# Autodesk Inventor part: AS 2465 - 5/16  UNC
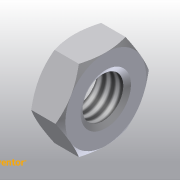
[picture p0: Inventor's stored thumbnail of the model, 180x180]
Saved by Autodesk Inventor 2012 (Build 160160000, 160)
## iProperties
Library Location: C:\Program Files\Local\Autodesk\Inventor 6\content
Library: local
SubLibrary: AS
Family: 79
Member: 20
Member Major Revision: 1
Member Minor Revision: 1
Comments: To add or edit properties for Autodesk Inventor files, use iProperties.
Company: Autodesk
Created: 2002-10
Part Number: AS 2465 - 5/16  UNC
Vendor: Autodesk Inc.
Document SubType Name: Modeling
Designer: Lieven Grauls
Description: Hexagon Thin Nut
Standard: AS 2465 5/16  UNC
Project: Valve Techcamp 2008
Density: 1 g/cm^3
Mass: 0.520705 g
Surface Area: 5.06999 cm^2
Volume: 0.520705 cm^3
Material: Default
Alert: To add or edit properties for Autodesk Inventor files, use iProperties.
Control State: 0
Master: False
Checked Out: False
Shininess: 64.0
Length Units: 11269
Angle Units: 11279
Time Units: 11290
Mass Units: 11283
Length Display Precision: 3
Angle Display Precision: 2
Compacted: True
EGR: 3
Density: 0.0
Volumn: 0.0
Area: 0.0
PropertySet Name: Model Information
Author: Lieven Grauls
Revision Number: 1
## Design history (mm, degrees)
sketch "Sketch1"
  geometry: L1 (-7.332, 0)-(-3.666, 6.35); L2 (-3.666, 6.35)-(3.666, 6.35); L3 (3.666, 6.35)-(7.332, 0); L4 (7.332, 0)-(3.666, -6.35); L5 (3.666, -6.35)-(-3.666, -6.35); L6 (-3.666, -6.35)-(-7.332, 0); 2 further points
  constraints: 12 end point, 1 coincident, 1 horizontal, 11 other
  dimensions: "d0" = 14.6647 distance of L3.end L1.start (= 1.1547 x SW)
extrude "Body" new body sketch "Sketch1" distance "d1" = 4.953 (= KOH); taper "d2" = 0 deg
revolve "Chamfer1" stored, may be unused: angle "d7" = 90 deg
sketch "Sketch3"
  geometry: A1 r 6.35 centre (0, 0) between (-3.175, -5.499) and (3.175, -5.499) reference; 1 further point
  constraints: 1 coincident
hole "Thread" sketch "Sketch3" diameter "d25" = 6.4008; stored, may be unused: countersink angle "d29" = 82 deg, drill point angle "d31" = 118 deg; dims "d26" = 6, "d27" = 4, "d28" = 2, "d30" = 8
node "Volumenkörper1"
node "Volumenkörpern"
node "Oberflächenkörpern"
chamfer "Chamfer2" distance "d8" = 0.76379 (= -0.5 x GD1 + 0.5 x NND); stored, may be unused: angle "d9" = 30 deg, second distance "d40" = 0.76379 (= -0.5 x GD1 + 0.5 x NND)
chamfer "Chamfer3" distance "d10" = 0.76379 (= -0.5 x GD1 + 0.5 x NND); stored, may be unused: angle "d11" = 30 deg, second distance "d41" = 0.76379 (= -0.5 x GD1 + 0.5 x NND)
sketch "Sketch2"
  geometry: L1 (0, 3.666)-(0, 7.332) reference; L2 (0, 7.332)-(4.953, 7.332) reference; L3 (4.953, 3.666)-(4.953, 7.332) reference; L4 (-0.495, 0)-(6.439, 0) reference; L5 (0.567, 7.332)-(0, 6.35); L6 (4.386, 7.332)-(4.953, 6.35)
  constraints: 4 end point, 4 point on line
  dimensions: "d3" = 30 deg angle of L1 L5 (= ANG1); "d4" = 30 deg angle of L3 L6 (= ANG2); "d5" = 12.7 diameter of L5.end L4 (= SW0); "d6" = 12.7 diameter of L6.end L4 (= SW01)
other parameters: "ANG1" = 30 deg [user parameter; used in 1 equation term], "ANG2" = 30 deg [user parameter; used in 1 equation term], "NND" = 7.9375 [user parameter; used in 4 equation terms], "KOH" = 4.953 [user parameter; used in 1 equation term], "SW" = 12.7 [user parameter; used in 4 equation terms], "SW0" = 12.7 (= SW) [user parameter; used in 1 equation term], "SW01" = 12.7 (= SW) [user parameter; used in 1 equation term], "GD1" = 6.40993 (computed from THREADDIA, TPU, TOA) [user parameter; used in 4 equation terms], "d13" = 0, "d14" = 0, "d39" = 0, "TOA" = 30 deg [user parameter; used in 1 equation term], "PTC" = 1.41111 (computed from TPU) [user parameter], "THREADDIA" = 7.9375 [user parameter; used in 1 equation term], "E0" = 14.6685 (= 1.155 x SW) [user parameter]
